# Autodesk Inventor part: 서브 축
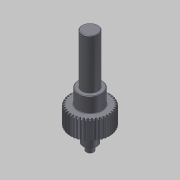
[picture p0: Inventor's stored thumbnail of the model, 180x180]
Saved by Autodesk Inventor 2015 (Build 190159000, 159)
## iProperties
Created: 2016-02
Part Number: 서브 축
Material: 강철, 연강
Document SubType Name: Modeling
Designer: mdu
Categories: <?xml version="1.0" encoding="UTF-16"?> <MemberInstance><Categories><FamilyTemplate><FamilyTemplateParameter ValueType="xs:double" Id="1" ObjectReferenceKey="da
Density: 7.86 g/cm^3
Appearance: Steel
Mass: 377.12 g
Surface Area: 123.805 cm^2
Volume: 47.9796 cm^3
CustomPartVersion: 1
Author: mdu
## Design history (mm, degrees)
sketch "Sketch1"
  geometry: C1 r 21 at (0, 0)
  constraints: 1 centre point
  dimensions: "d0" = 42 diameter of C1 (= da_da)
extrude "Extrusion1" new body sketch "Sketch1" distance "d1" = 20 (= da_b); taper "d2" = 0 deg
workplane "Work Plane2"
feature "피치 지름" dims "d4" = 10, "d5" = 0
workplane "Work Plane8"
workplane "Work Plane9"
chamfer "모따기1" distance "d49" = 1; stored, may be unused: second distance "d50" = 2, angle "d51" = 45 deg
sketch "스케치3"
  geometry: C1 r 12.5 at (0, 0); 1 further point
  constraints: 1 centre point, 1 coincident
  dimensions: "d52" = 25 diameter of C1
extrude "돌출2" join sketch "스케치3" distance "d53" = 16; taper "d54" = 0 deg
sketch "스케치4"
  geometry: C1 r 8.5 at (0, 0); 1 further point
  constraints: 1 centre point, 1 coincident
  dimensions: "d55" = 17 diameter of C1
extrude "돌출3" join sketch "스케치4" distance "d56" = 53; taper "d57" = 0 deg
sketch "스케치5"
  geometry: C1 r 7.5 at (0, 0); 1 further point
  constraints: 1 centre point, 1 coincident
  dimensions: "d62" = 15 diameter of C1
extrude "돌출4" join sketch "스케치5" distance "d63" = 16; taper "d64" = 0 deg
sketch "스케치6"
  geometry: C1 r 4 at (0, 0); 1 further point
  constraints: 1 centre point, 1 coincident
  dimensions: "d65" = 8 diameter of C1
extrude "돌출5" join sketch "스케치6" distance "d66" = 7; taper "d67" = 0 deg
chamfer "모따기2" distance "d58" = 0.5; stored, may be unused: second distance "d59" = 2, angle "d60" = 45 deg
fillet "모깎기1" dims "d61" = 0.5
feature "스퍼 기어" dims "da_b" = 20, "da_d" = 40, "da_aw" = 31, "da_da" = 42, "da_df" = 37.5, "da_dw" = 40, angle "da_beta" = 0 deg, "da_lefttooth" = 0, "da_righttooth" = 0
body "Solid1"
sketch "Sketch2"
  geometry: C1 r 21 at (0, 0) reference; C2 r 20 at (0, 0)
  constraints: 1 centre point, 1 coincident
  dimensions: "d3" = 40 diameter of C2 (= da_dw)
body "Srf1"
other parameters: "d16" = 31 (= da_aw), "d17" = 0, "d34" = 4.5 deg (computed from da_z), "d39" = 0, "d41" = 0, "d43" = 31 (= da_aw), "d46" = 31 (= da_aw), "d47" = 0, "d48" = 0
